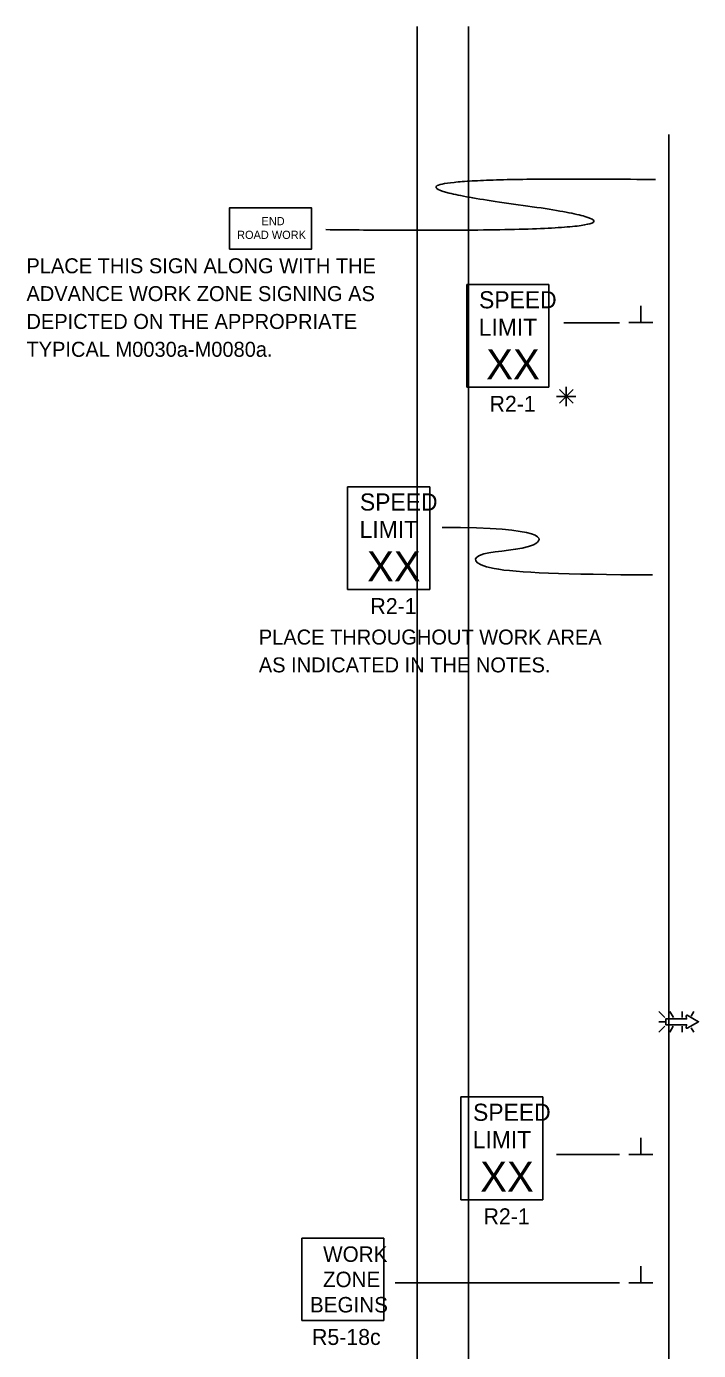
# Model space of a CAD drawing. Extents: x 16744 to 19504, y 5731 to 6974.
# Drawn here: x 16798 to 17112, y 6356 to 6974 of the extents above; entities that cross this region are included whole.
import ezdxf

# ---------------------------------------------------------------- set-up
doc = ezdxf.new("R2010")
doc.units = 0
for name, color, linetype in [('ALI_LEGAL_EX', 7, 'Continuous'), ('PAVT_EDGE_EX', 7, 'Continuous'), ('TRAFFIC_SIGNS_PR', 7, 'Continuous'), ('TYPICAL_TEXT_DIMEN_PR', 7, 'Continuous')]:
    doc.layers.add(name, color=color, linetype=linetype)

msp = doc.modelspace()

# ---------------------------------------------------------------- linework, layer by layer
at = {"layer": 'ALI_LEGAL_EX'}
for p, q in [((16980.68, 6974.12), (16980.68, 6155.98)), ((17004.68, 6974.12), (17004.68, 6155.98)), ((16980.68, 6922.21), (16980.68, 6058.3)), ((17004.68, 6922.21), (17004.68, 6058.3))]:
    msp.add_line(p, q, dxfattribs=at)
msp.add_lwpolyline([(17004.68, 6949.12), (17004.68, 6974.12)], dxfattribs=at)
at = {"layer": 'PAVT_EDGE_EX'}
msp.add_line((17098.25, 6923.7), (17098.25, 6094.51), dxfattribs=at)
at = {"layer": 'TRAFFIC_SIGNS_PR'}
for p, q in [((17003.82, 6853.63), (17042.22, 6853.63)), ((17003.82, 6805.63), (17003.82, 6853.63)), ((17042.22, 6805.63), (17042.22, 6853.63)), ((17003.82, 6805.63), (17042.22, 6805.63)), ((16948.16, 6759.19), (16986.56, 6759.19)), ((16948.16, 6711.19), (16948.16, 6759.19)), ((16986.56, 6711.19), (16986.56, 6759.19)), ((16948.16, 6711.19), (16986.56, 6711.19)), ((17096.41, 6511.37), (17093.59, 6514.19)), ((17100.36, 6511.37), (17098.73, 6514.19)), ((17104.5, 6511.37), (17104.5, 6514.19)), ((17108.68, 6512.01), (17109.94, 6514.19)), ((17096.41, 6509.34), (17093.59, 6509.34)), ((17096.41, 6507.31), (17093.59, 6504.49)), ((17098.71, 6504.49), (17100.34, 6507.31)), ((17104.5, 6507.31), (17104.5, 6504.49)), ((17109.97, 6504.49), (17108.76, 6506.58)), ((17001.02, 6474.23), (17039.42, 6474.23)), ((17001.02, 6426.23), (17001.02, 6474.23)), ((17039.42, 6426.23), (17039.42, 6474.23)), ((17001.02, 6426.23), (17039.42, 6426.23)), ((16926.75, 6369.86), (16926.75, 6408.26)), ((16926.75, 6408.26), (16965.15, 6408.26)), ((16965.15, 6369.86), (16965.15, 6408.26)), ((16926.75, 6369.86), (16965.15, 6369.86))]:
    msp.add_line(p, q, dxfattribs=at)
msp.add_lwpolyline([(16892.94, 6870.17), (16931.34, 6870.17), (16931.34, 6889.37), (16892.94, 6889.37)], close=True, dxfattribs=at)
for points in [[(17106.32, 6506.66), (17106.55, 6507.95), (17096.83, 6507.95), (17096.83, 6510.7), (17106.55, 6510.7), (17106.32, 6512)], [(17106.82, 6512.36), (17112.13, 6509.34), (17106.82, 6506.3)]]:
    msp.add_lwpolyline(points, dxfattribs=at)
for centre, start, end in [((17106.66, 6512.06), 61.10835, 189.26922), ((17106.66, 6506.6), 170.04067, 298.51671)]:
    msp.add_arc(centre, 0.341, start, end, dxfattribs=at)
msp.add_open_spline([(17092.04, 6902.64), (16926.52, 6904.65), (17129.58, 6877.07), (16938.01, 6879.24)], degree=2, dxfattribs=at)
at = {"layer": 'TYPICAL_TEXT_DIMEN_PR'}
for p, q in [((17085.12, 6835.82), (17085.12, 6843.61)), ((17049.25, 6835.79), (17075.25, 6835.79)), ((17079.5, 6835.82), (17090.75, 6835.82)), ((17050.36, 6801.37), (17045.83, 6801.37)), ((17047.17, 6804.56), (17053.55, 6798.18)), ((17053.55, 6804.56), (17047.17, 6798.18)), ((17050.36, 6801.37), (17050.36, 6805.82)), ((17050.36, 6801.37), (17053.55, 6801.37)), ((17050.36, 6801.37), (17054.84, 6801.37)), ((17050.36, 6801.37), (17050.36, 6796.87)), ((17085.12, 6447.44), (17085.12, 6455.22)), ((17045.78, 6447.44), (17075.25, 6447.44)), ((17079.5, 6447.44), (17090.75, 6447.44)), ((17085.12, 6387.44), (17085.12, 6395.22)), ((16970.46, 6387.44), (17075.25, 6387.44)), ((17079.5, 6387.44), (17090.75, 6387.44))]:
    msp.add_line(p, q, dxfattribs=at)
msp.add_open_spline([(16992.4, 6740.19), (17040.87, 6740.19), (17040.87, 6729.43), (17005.95, 6729.43), (17005.95, 6719.77), (17048.81, 6718.25), (17090.63, 6717.99)], degree=3, dxfattribs=at)

# ---------------------------------------------------------------- texts
at = {"layer": 'TRAFFIC_SIGNS_PR'}
for s, height, p in [('END', 3.831, (16907.95, 6881.3)), ('ROAD WORK', 3.831, (16896.55, 6874.91)), ('PLACE THIS SIGN ALONG WITH THE', 7, (16798.12, 6858.87)), ('ADVANCE WORK ZONE SIGNING AS', 7, (16798.12, 6845.87)), ('SPEED', 8, (17009.58, 6842.5)), ('DEPICTED ON THE APPROPRIATE', 7, (16798.12, 6832.87)), ('LIMIT', 8, (17009.42, 6829.7)), ('TYPICAL M0030a-M0080a.', 7, (16798.12, 6819.87)), ('XX', 14.031, (17012.93, 6809.39)), ('R2-1', 7.44, (17014.49, 6794.19)), ('SPEED', 8, (16953.92, 6748.06)), ('LIMIT', 8, (16953.76, 6735.26)), ('XX', 14.031, (16957.27, 6714.95)), ('R2-1', 7.44, (16958.83, 6699.75)), ('PLACE THROUGHOUT WORK AREA', 7, (16906.69, 6685.5)), ('AS INDICATED IN THE NOTES.', 7, (16906.69, 6672.5)), ('SPEED', 8, (17006.78, 6463.09)), ('LIMIT', 8, (17006.62, 6450.29)), ('XX', 14.031, (17010.13, 6429.99)), ('R2-1', 7.44, (17011.69, 6414.79)), ('WORK', 7.217, (16936.75, 6397.23)), ('ZONE', 7.217, (16936.63, 6385.42)), ('BEGINS', 7.217, (16930.56, 6373.61)), ('R5-18c', 7.44, (16931.56, 6358.42))]:
    msp.add_text(s, height=height, dxfattribs=at).set_placement(p)

doc.saveas('drawing.dxf')
